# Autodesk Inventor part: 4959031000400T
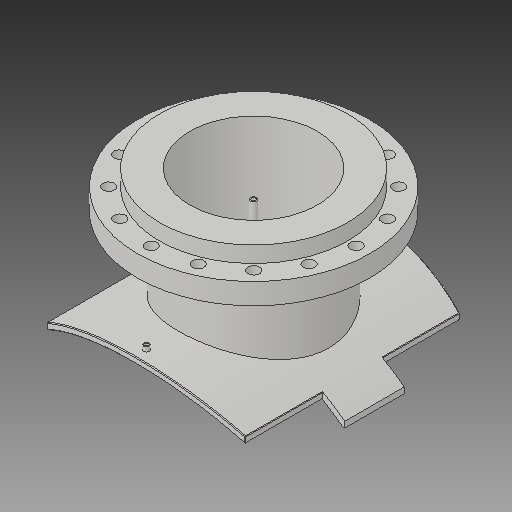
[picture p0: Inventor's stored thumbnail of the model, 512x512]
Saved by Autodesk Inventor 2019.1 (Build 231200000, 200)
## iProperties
Created: 2017-10
Part Number: 4959031000400T
Material: Generic
Description: PLASSON FLANGED BRANCH SADDLE 1000X400
Document SubType Name: Modeling
Designer: KIM
Mass: 2339.99 g
Surface Area: 3251.55 cm^2
Volume: 2339.99 cm^3
Density: 1 g/cm^3
Appearance: Default
Author: KIM
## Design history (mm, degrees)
derived "495904_495903.ipt"
feature "Solid1::495904_495903.ipt"
feature "Solid2::495904_495903.ipt"
tag "TaggingFeature1"
body "Solid1"
other parameters: "d1" = 15, "d2" = 506.7, "d4" = 0, "d6" = 152.5, "d7" = 0, "d12" = 525.6, "d13" = 14, "d14" = 274.5, "d16" = 5 deg, "d18" = 4, "d19" = 14, "d20" = 0, "d21" = 3, "d22" = 0, "d23" = 795, "d36" = 274.5, "d38" = 0, "d39" = 2, "d41" = 327, "d42" = 482, "d43" = 595, "d44" = 224, "d46" = 385.6, "d47" = 16, "d48" = 10.4, "d49" = 196, "d53" = 0, "d55" = 262.5, "d57" = 0, "d59" = 360 deg, "d61" = 54, "d63" = 0, "d67" = 15, "d70" = 0, "d71" = 2, "d72" = 563, "d_1" = 482, "B_" = 563, "x_" = 15, "D_" = 16, "DN_" = 327, "D_1" = 595, "t_" = 54, "Dp_" = 525
